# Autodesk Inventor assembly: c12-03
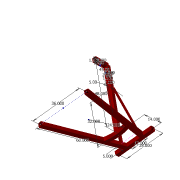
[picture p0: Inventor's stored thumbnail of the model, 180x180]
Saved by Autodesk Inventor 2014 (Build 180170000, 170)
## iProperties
Created: 2011-01
Part Number: c12-03
Document SubType Name: Assembly
Designer: Thom Tremblay
_SolveAssemblyDoc: Frame Generator Solve Assembly
_Version: 15.0.0
Author: Thom Tremblay
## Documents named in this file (3)
- C:\Inventor 2014 Essentials\Assemblies\Chapter 12\c12-03.iam
- C:\Inventor 2014 Essentials\Assemblies\Chapter 12\Frame\Frame c12-03.iam
- C:\Inventor 2014 Essentials\Parts\Chapter 12\c12-02.ipt
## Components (2 placed, 2 different names)
1. c12-02:1
2. Frame c12-03:1 [sub-assembly]
